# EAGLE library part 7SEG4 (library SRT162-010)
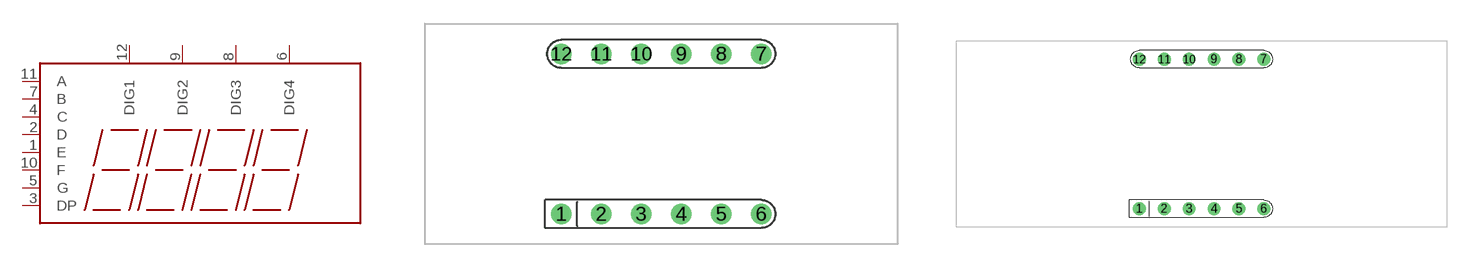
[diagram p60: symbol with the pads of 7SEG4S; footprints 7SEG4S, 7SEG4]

Designator prefix M

## 7SEG4S  [7SEG4S]
1  E  pas
2  D  pas
3  DP  pas
4  C  pas
5  G  pas
6  DIG4  pas
7  B  pas
8  DIG3  pas
9  DIG2  pas
10  F  pas
11  A  pas
12  DIG1  pas

## 7SEG4  [7SEG4]
Pads as for 7SEG4S

## 7SEG43  [7SEG3]
Pads as for 7SEG4S

## Footprint 7SEG4S (pad centres in mm)
drill 0.8 round: 1 -6.35,-5.08; 2 -3.81,-5.08; 3 -1.27,-5.08; 4 1.27,-5.08; 5 3.81,-5.08; 6 6.35,-5.08; 7 6.35,5.08; 8 3.81,5.08; 9 1.27,5.08; 10 -1.27,5.08; 11 -3.81,5.08; 12 -6.35,5.08

## Footprint 7SEG4 (pad centres in mm)
drill 0.8 round: 1 -6.35,-7.62; 2 -3.81,-7.62; 3 -1.27,-7.62; 4 1.27,-7.62; 5 3.81,-7.62; 6 6.35,-7.62; 7 6.35,7.62; 8 3.81,7.62; 9 1.27,7.62; 10 -1.27,7.62; 11 -3.81,7.62; 12 -6.35,7.62

## Footprint 7SEG3 (pad centres in mm)
drill 0.8 round: 1 -6.35,-7.62; 2 -3.81,-7.62; 3 -1.27,-7.62; 4 1.27,-7.62; 5 3.81,-7.62; 6 6.35,-7.62; 7 6.35,7.62; 8 3.81,7.62; 9 1.27,7.62; 10 -1.27,7.62; 11 -3.81,7.62; 12 -6.35,7.62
